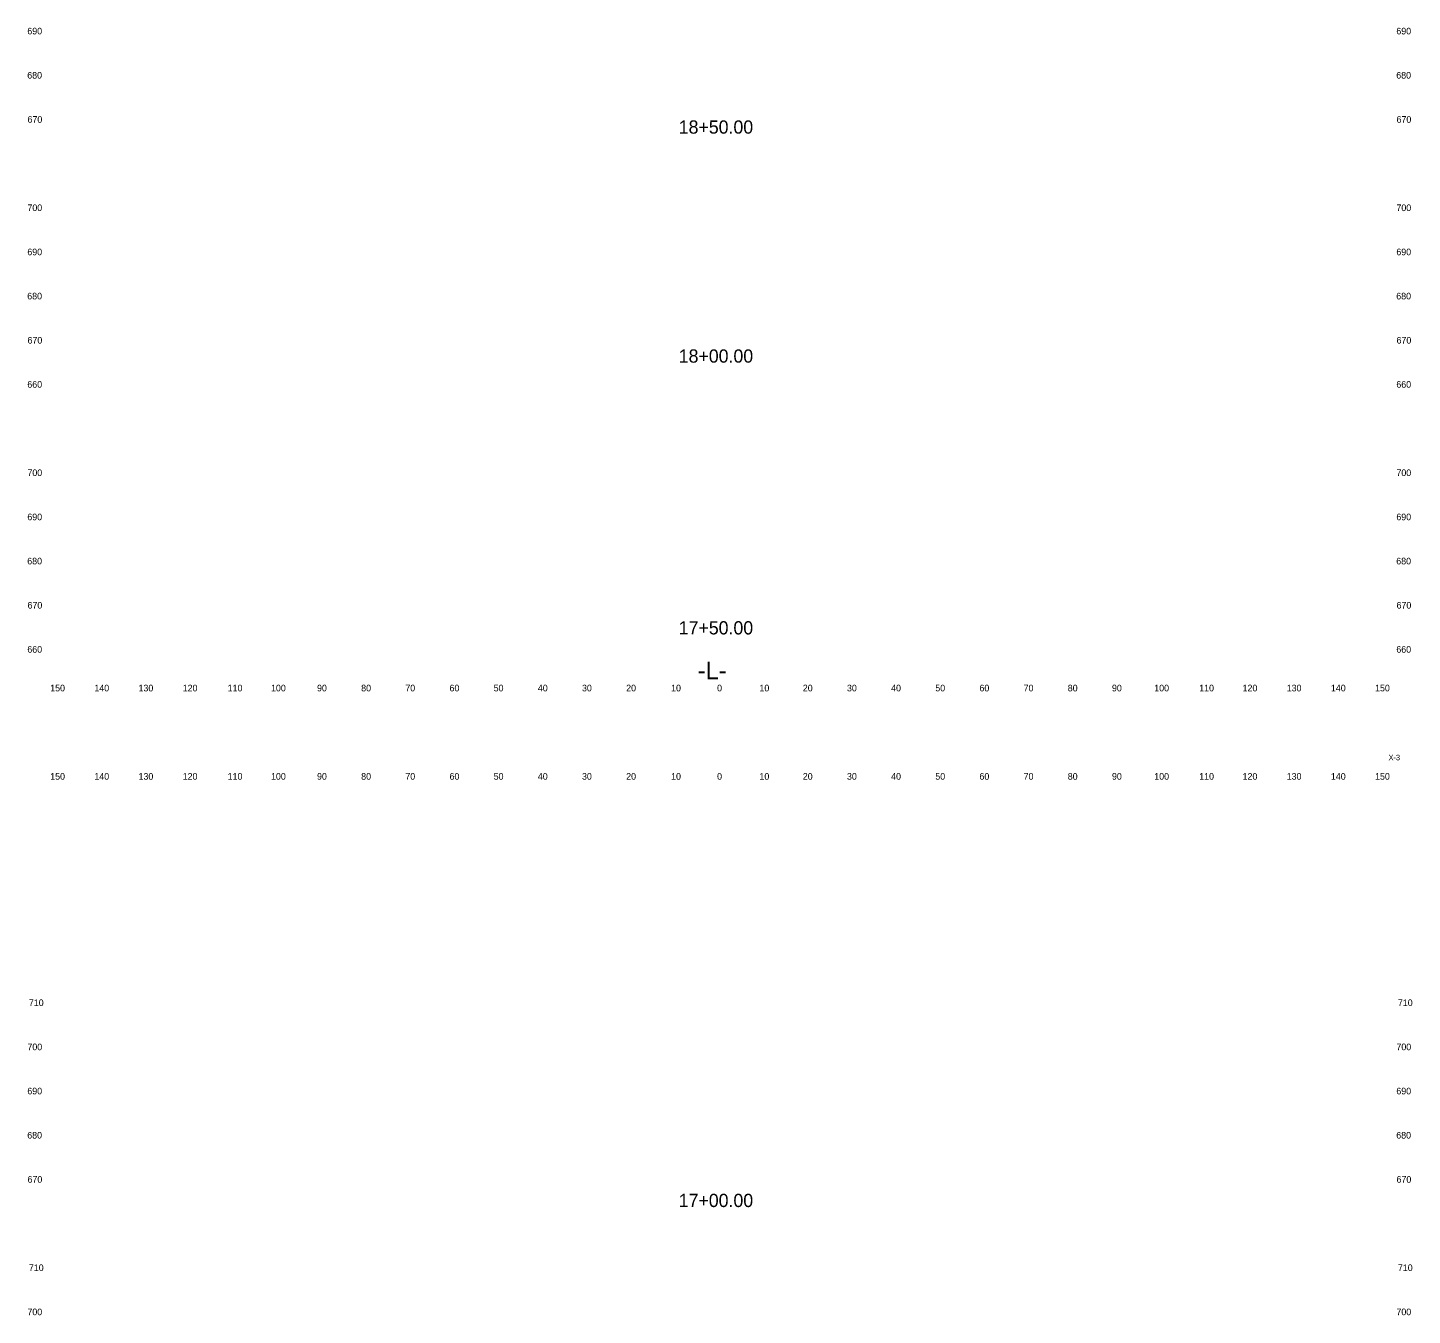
# Model space of a CAD drawing. Extents: x 3 to 317, y 0 to 2407.
# Drawn here: x 3.3 to 316.9, y 300 to 591.5 of the extents above; entities that cross this region are included whole.
import ezdxf

# ---------------------------------------------------------------- set-up
doc = ezdxf.new("R2010")
doc.units = 0
for name, color, linetype in [('Prop XS Ditch Standard Text', 7, 'Continuous'), ('Prop XS Dump Level', 7, 'Continuous'), ('Prop XS SE Text', 7, 'Continuous'), ('Prop XS Sheet Number', 7, 'Continuous'), ('Prop XS SS Elevation Text', 7, 'Continuous')]:
    doc.layers.add(name, color=color, linetype=linetype)

msp = doc.modelspace()

# ---------------------------------------------------------------- texts
at = {"layer": 'Prop XS Ditch Standard Text'}
for s, p in [('18+50.00', (150.77, 567.53)), ('18+00.00', (150.77, 515.68)), ('17+50.00', (150.77, 454.14)), ('17+00.00', (150.77, 324.49))]:
    msp.add_text(s, height=3, dxfattribs=at).set_placement(p)
at = {"layer": 'Prop XS Dump Level'}
for s, p in [('150', (8.44, 441.25)), ('140', (18.44, 441.25)), ('130', (28.44, 441.25)), ('120', (38.44, 441.25)), ('110', (48.62, 441.25)), ('100', (58.44, 441.25)), ('90', (68.86, 441.25)), ('80', (78.86, 441.25)), ('70', (88.86, 441.25)), ('60', (98.86, 441.25)), ('50', (108.86, 441.25)), ('40', (118.86, 441.25)), ('30', (128.86, 441.25)), ('20', (138.86, 441.25)), ('10', (149.04, 441.25)), ('0', (159.45, 441.25)), ('10', (169.04, 441.25)), ('20', (178.86, 441.25)), ('30', (188.86, 441.25)), ('40', (198.86, 441.25)), ('50', (208.86, 441.25)), ('60', (218.86, 441.25)), ('70', (228.86, 441.25)), ('80', (238.86, 441.25)), ('90', (248.86, 441.25)), ('100', (258.44, 441.25)), ('110', (268.62, 441.25)), ('120', (278.44, 441.25)), ('130', (288.44, 441.25)), ('140', (298.44, 441.25)), ('150', (308.44, 441.25)), ('150', (8.44, 421.25)), ('140', (18.44, 421.25)), ('130', (28.44, 421.25)), ('120', (38.44, 421.25)), ('110', (48.62, 421.25)), ('100', (58.44, 421.25)), ('90', (68.86, 421.25)), ('80', (78.86, 421.25)), ('70', (88.86, 421.25)), ('60', (98.86, 421.25)), ('50', (108.86, 421.25)), ('40', (118.86, 421.25)), ('30', (128.86, 421.25)), ('20', (138.86, 421.25)), ('10', (149.04, 421.25)), ('0', (159.45, 421.25)), ('10', (169.04, 421.25)), ('20', (178.86, 421.25)), ('30', (188.86, 421.25)), ('40', (198.86, 421.25)), ('50', (208.86, 421.25)), ('60', (218.86, 421.25)), ('70', (228.86, 421.25)), ('80', (238.86, 421.25)), ('90', (248.86, 421.25)), ('100', (258.44, 421.25)), ('110', (268.62, 421.25)), ('120', (278.44, 421.25)), ('130', (288.44, 421.25)), ('140', (298.44, 421.25)), ('150', (308.44, 421.25))]:
    msp.add_text(s, height=1.5, dxfattribs=at).set_placement(p)
at = {"layer": 'Prop XS SE Text'}
for s, p in [('690', (3.26, 590)), ('690', (313.26, 590)), ('680', (3.24, 580)), ('680', (313.24, 580)), ('670', (3.3, 570)), ('670', (313.3, 570)), ('700', (3.28, 550)), ('700', (313.28, 550)), ('690', (3.26, 540)), ('690', (313.26, 540)), ('680', (3.24, 530)), ('680', (313.24, 530)), ('670', (3.3, 520)), ('670', (313.3, 520)), ('660', (3.26, 510)), ('660', (313.26, 510)), ('700', (3.28, 490)), ('700', (313.28, 490)), ('690', (3.26, 480)), ('690', (313.26, 480)), ('680', (3.24, 470)), ('680', (313.24, 470)), ('670', (3.3, 460)), ('670', (313.3, 460)), ('660', (3.26, 450)), ('660', (313.26, 450)), ('710', (3.61, 370)), ('710', (313.61, 370)), ('700', (3.28, 360)), ('700', (313.28, 360)), ('690', (3.26, 350)), ('690', (313.26, 350)), ('680', (3.24, 340)), ('680', (313.24, 340)), ('670', (3.3, 330)), ('670', (313.3, 330)), ('710', (3.61, 310)), ('710', (313.61, 310)), ('700', (3.28, 300)), ('700', (313.28, 300))]:
    msp.add_text(s, height=1.5, dxfattribs=at).set_placement(p)
at = {"layer": 'Prop XS Sheet Number'}
msp.add_text('X-3', height=1.25, dxfattribs=at).set_placement((311.5, 425.65))
at = {"layer": 'Prop XS SS Elevation Text'}
msp.add_text('-L-', height=4, dxfattribs=at).set_placement((155.06, 444))

doc.saveas('drawing.dxf')
